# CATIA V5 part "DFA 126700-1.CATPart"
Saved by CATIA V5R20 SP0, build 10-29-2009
Part number: DFA 126700-1
Revision: ANY
Definition: UNKNOWN
Nomenclature: DFA 126700-1
Source: Unknown
Bounding box of the stored display mesh (mm): x -3.804 to 3.804, y 0.2 to 2.5, z -4 to 4
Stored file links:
  C:\Users\Utente\Desktop\IO LAVORO\3D X SITO CF\CUMSA\3D files FA\FA 126712-21\DFA 126700-1.CATPart
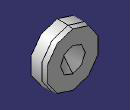
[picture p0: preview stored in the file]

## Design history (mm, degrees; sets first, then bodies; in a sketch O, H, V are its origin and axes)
Body1 "Cortar-Extruir1" (main body)
  Solid1: solid without history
